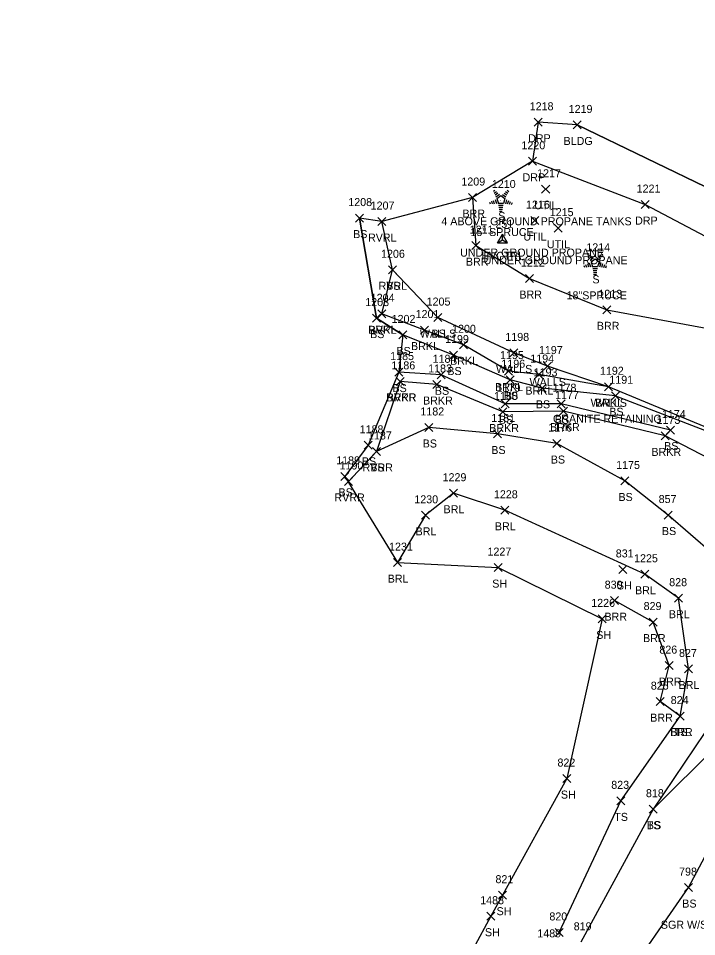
# Model space of a CAD drawing. Extents: x 1639430 to 1640195, y 612006 to 612917.
# Drawn here: x 1639596.7 to 1639766.2, y 612515.2 to 612744.6 of the extents above; entities that cross this region are included whole.
import ezdxf

# ---------------------------------------------------------------- set-up
doc = ezdxf.new("R2010")
doc.units = 0
for name, color, linetype in [('C_A', 7, 'Continuous'), ('C_I', 7, 'Continuous'), ('CPSM', 7, 'Continuous'), ('L_A', 7, 'Continuous'), ('L_C', 7, 'Continuous'), ('L_I', 7, 'Continuous'), ('L_TIC', 7, 'Continuous'), ('LABL', 7, 'Continuous'), ('LAWE', 7, 'Continuous'), ('LBC', 7, 'Continuous'), ('LELB', 7, 'Continuous'), ('LSOGP', 7, 'Continuous'), ('LTC', 7, 'Continuous'), ('LWS', 7, 'Continuous'), ('R_A', 7, 'Continuous'), ('R_C', 7, 'Continuous'), ('R_I', 7, 'Continuous'), ('R_TIC', 7, 'Continuous'), ('RDP', 7, 'Continuous'), ('U_A', 7, 'Continuous'), ('U_C', 7, 'Continuous'), ('U_I', 7, 'Continuous'), ('UDEFAULT', 7, 'Continuous')]:
    doc.layers.add(name, color=color, linetype=linetype)

msp = doc.modelspace()

# ---------------------------------------------------------------- linework, layer by layer
at = {"layer": 'CPSM'}
for p, q in [((1639716.47, 612688.55), (1639717.72, 612690.71)), ((1639718.97, 612688.55), (1639717.72, 612690.71)), ((1639717.72, 612689.27), (1639717.72, 612690.71)), ((1639716.47, 612688.55), (1639717.72, 612689.27)), ((1639716.47, 612688.55), (1639718.97, 612688.55)), ((1639717.72, 612689.27), (1639717.72, 612689.27)), ((1639717.72, 612689.27), (1639718.97, 612688.55))]:
    msp.add_line(p, q, dxfattribs=at)
at = {"layer": 'L_TIC'}
for points in [[(1639735.37, 612716.97), (1639737.37, 612718.97)], [(1639737.37, 612716.97), (1639735.37, 612718.97)], [(1639709.2, 612698.83), (1639711.2, 612700.83)], [(1639711.2, 612698.83), (1639709.2, 612700.83)], [(1639680.93, 612693.7), (1639682.93, 612695.7)], [(1639682.93, 612693.7), (1639680.93, 612695.7)], [(1639686.52, 612692.83), (1639688.52, 612694.83)], [(1639688.52, 612692.83), (1639686.52, 612694.83)], [(1639710.05, 612686.81), (1639712.05, 612688.81)], [(1639712.05, 612686.81), (1639710.05, 612688.81)], [(1639689.17, 612680.78), (1639691.17, 612682.78)], [(1639691.17, 612680.78), (1639689.17, 612682.78)], [(1639689.17, 612680.78), (1639691.17, 612682.78)], [(1639691.17, 612680.78), (1639689.17, 612682.78)], [(1639723.43, 612678.59), (1639725.43, 612680.59)], [(1639725.43, 612678.59), (1639723.43, 612680.59)], [(1639686.53, 612669.78), (1639688.53, 612671.78)], [(1639688.53, 612669.78), (1639686.53, 612671.78)], [(1639686.53, 612669.78), (1639688.53, 612671.78)], [(1639688.53, 612669.78), (1639686.53, 612671.78)], [(1639742.79, 612670.78), (1639744.79, 612672.78)], [(1639744.79, 612670.78), (1639742.79, 612672.78)], [(1639685.17, 612668.71), (1639687.17, 612670.71)], [(1639687.17, 612668.71), (1639685.17, 612670.71)], [(1639700.51, 612668.84), (1639702.51, 612670.84)], [(1639702.51, 612668.84), (1639700.51, 612670.84)], [(1639700.51, 612668.84), (1639702.51, 612670.84)], [(1639702.51, 612668.84), (1639700.51, 612670.84)], [(1639697.19, 612665.72), (1639699.19, 612667.72)], [(1639699.19, 612665.72), (1639697.19, 612667.72)], [(1639691.76, 612664.5), (1639693.76, 612666.5)], [(1639693.76, 612664.5), (1639691.76, 612666.5)], [(1639706.95, 612662.04), (1639708.95, 612664.04)], [(1639708.95, 612662.04), (1639706.95, 612664.04)], [(1639704.48, 612659.48), (1639706.48, 612661.48)], [(1639706.48, 612659.48), (1639704.48, 612661.48)], [(1639719.54, 612660.01), (1639721.54, 612662.01)], [(1639721.54, 612660.01), (1639719.54, 612662.01)], [(1639727.93, 612656.72), (1639729.93, 612658.72)], [(1639729.93, 612656.72), (1639727.93, 612658.72)], [(1639690.76, 612655.22), (1639692.76, 612657.22)], [(1639692.76, 612655.22), (1639690.76, 612657.22)], [(1639701.36, 612654.54), (1639703.36, 612656.54)], [(1639703.36, 612654.54), (1639701.36, 612656.54)], [(1639718.22, 612655.47), (1639720.22, 612657.47)], [(1639720.22, 612655.47), (1639718.22, 612657.47)], [(1639718.6, 612653.32), (1639720.6, 612655.32)], [(1639720.6, 612653.32), (1639718.6, 612655.32)], [(1639725.78, 612654.6), (1639727.78, 612656.6)], [(1639727.78, 612654.6), (1639725.78, 612656.6)], [(1639691.12, 612652.9), (1639693.12, 612654.9)], [(1639693.12, 612652.9), (1639691.12, 612654.9)], [(1639691.12, 612652.9), (1639693.12, 612654.9)], [(1639693.12, 612652.9), (1639691.12, 612654.9)], [(1639700.25, 612652.12), (1639702.25, 612654.12)], [(1639702.25, 612652.12), (1639700.25, 612654.12)], [(1639726.6, 612651.17), (1639728.6, 612653.17)], [(1639728.6, 612651.17), (1639726.6, 612653.17)], [(1639743.19, 612651.55), (1639745.19, 612653.55)], [(1639745.19, 612651.55), (1639743.19, 612653.55)], [(1639743.19, 612651.55), (1639745.19, 612653.55)], [(1639745.19, 612651.55), (1639743.19, 612653.55)], [(1639744.95, 612649.31), (1639746.95, 612651.31)], [(1639746.95, 612649.31), (1639744.95, 612651.31)], [(1639717.37, 612647.3), (1639719.37, 612649.3)], [(1639719.37, 612647.3), (1639717.37, 612649.3)], [(1639731.36, 612647.32), (1639733.36, 612649.32)], [(1639733.36, 612647.32), (1639731.36, 612649.32)], [(1639716.8, 612645.25), (1639718.8, 612647.25)], [(1639718.8, 612645.25), (1639716.8, 612647.25)], [(1639731.98, 612645.48), (1639733.98, 612647.48)], [(1639733.98, 612645.48), (1639731.98, 612647.48)], [(1639698.31, 612641.38), (1639700.31, 612643.38)], [(1639700.31, 612641.38), (1639698.31, 612643.38)], [(1639715.46, 612639.76), (1639717.46, 612641.76)], [(1639717.46, 612639.76), (1639715.46, 612641.76)], [(1639758.66, 612640.73), (1639760.66, 612642.73)], [(1639760.66, 612640.73), (1639758.66, 612642.73)], [(1639730.32, 612637.37), (1639732.32, 612639.37)], [(1639732.32, 612637.37), (1639730.32, 612639.37)], [(1639757.33, 612639.28), (1639759.33, 612641.28)], [(1639759.33, 612639.28), (1639757.33, 612641.28)], [(1639683.13, 612636.92), (1639685.13, 612638.92)], [(1639685.13, 612636.92), (1639683.13, 612638.92)], [(1639685.22, 612635.39), (1639687.22, 612637.39)], [(1639687.22, 612635.39), (1639685.22, 612637.39)], [(1639685.22, 612635.39), (1639687.22, 612637.39)], [(1639687.22, 612635.39), (1639685.22, 612637.39)], [(1639677.27, 612629.17), (1639679.27, 612631.17)], [(1639679.27, 612629.17), (1639677.27, 612631.17)], [(1639678.19, 612627.89), (1639680.19, 612629.89)], [(1639680.19, 612627.89), (1639678.19, 612629.89)], [(1639747.24, 612628.01), (1639749.24, 612630.01)], [(1639749.24, 612628.01), (1639747.24, 612630.01)], [(1639704.43, 612624.95), (1639706.43, 612626.95)], [(1639706.43, 612624.95), (1639704.43, 612626.95)], [(1639697.44, 612619.43), (1639699.44, 612621.43)], [(1639699.44, 612619.43), (1639697.44, 612621.43)], [(1639717.25, 612620.69), (1639719.25, 612622.69)], [(1639719.25, 612620.69), (1639717.25, 612622.69)], [(1639758.1, 612619.5), (1639760.1, 612621.5)], [(1639760.1, 612619.5), (1639758.1, 612621.5)], [(1639690.47, 612607.61), (1639692.47, 612609.61)], [(1639692.47, 612607.61), (1639690.47, 612609.61)], [(1639715.65, 612606.37), (1639717.65, 612608.37)], [(1639717.65, 612606.37), (1639715.65, 612608.37)], [(1639746.8, 612605.91), (1639748.8, 612607.91)], [(1639748.8, 612605.91), (1639746.8, 612607.91)], [(1639752.28, 612604.71), (1639754.28, 612606.71)], [(1639754.28, 612604.71), (1639752.28, 612606.71)], [(1639760.73, 612598.73), (1639762.73, 612600.73)], [(1639762.73, 612598.73), (1639760.73, 612600.73)], [(1639744.69, 612598.11), (1639746.69, 612600.11)], [(1639746.69, 612598.11), (1639744.69, 612600.11)], [(1639741.63, 612593.56), (1639743.63, 612595.56)], [(1639743.63, 612593.56), (1639741.63, 612595.56)], [(1639754.34, 612592.76), (1639756.34, 612594.76)], [(1639756.34, 612592.76), (1639754.34, 612594.76)], [(1639758.32, 612581.88), (1639760.32, 612583.88)], [(1639760.32, 612581.88), (1639758.32, 612583.88)], [(1639763.18, 612581.04), (1639765.18, 612583.04)], [(1639765.18, 612581.04), (1639763.18, 612583.04)], [(1639756.13, 612572.88), (1639758.13, 612574.88)], [(1639758.13, 612572.88), (1639756.13, 612574.88)], [(1639761.1, 612569.28), (1639763.1, 612571.28)], [(1639763.1, 612569.28), (1639761.1, 612571.28)], [(1639761.1, 612569.28), (1639763.1, 612571.28)], [(1639763.1, 612569.28), (1639761.1, 612571.28)], [(1639761.1, 612569.28), (1639763.1, 612571.28)], [(1639763.1, 612569.28), (1639761.1, 612571.28)], [(1639732.8, 612553.66), (1639734.8, 612555.66)], [(1639734.8, 612553.66), (1639732.8, 612555.66)], [(1639746.25, 612548.09), (1639748.25, 612550.09)], [(1639748.25, 612548.09), (1639746.25, 612550.09)], [(1639754.35, 612546.01), (1639756.35, 612548.01)], [(1639756.35, 612546.01), (1639754.35, 612548.01)], [(1639754.35, 612546.01), (1639756.35, 612548.01)], [(1639756.35, 612546.01), (1639754.35, 612548.01)], [(1639763.19, 612526.42), (1639765.19, 612528.42)], [(1639765.19, 612526.42), (1639763.19, 612528.42)], [(1639716.74, 612524.52), (1639718.74, 612526.52)], [(1639718.74, 612524.52), (1639716.74, 612526.52)], [(1639713.82, 612519.27), (1639715.82, 612521.27)], [(1639715.82, 612519.27), (1639713.82, 612521.27)], [(1639730.87, 612515.21), (1639732.87, 612517.21)], [(1639732.87, 612515.21), (1639730.87, 612517.21)]]:
    msp.add_lwpolyline(points, dxfattribs=at)
at = {"layer": 'LABL'}
for points in [[(1639710.2, 612699.83), (1639711.05, 612687.81), (1639724.43, 612679.59), (1639743.79, 612671.78), (1639774.03, 612666.16)], [(1639753.28, 612605.71), (1639718.25, 612621.69), (1639705.43, 612625.95), (1639698.44, 612620.43), (1639691.47, 612608.61)], [(1639761.73, 612599.73), (1639753.28, 612605.71)], [(1639762.1, 612570.28), (1639757.13, 612573.88), (1639759.32, 612582.88), (1639755.34, 612593.76), (1639745.69, 612599.11)], [(1639762.1, 612570.28), (1639764.18, 612582.04), (1639761.73, 612599.73)]]:
    msp.add_lwpolyline(points, dxfattribs=at)
at = {"layer": 'LAWE'}
for points in [[(1639687.53, 612670.78), (1639690.17, 612681.78), (1639687.52, 612693.83)], [(1639744.19, 612652.55), (1639726.78, 612655.6), (1639719.22, 612656.47), (1639707.95, 612663.04), (1639698.19, 612666.72), (1639687.53, 612670.78)], [(1639692.12, 612653.9), (1639686.22, 612636.39), (1639679.19, 612628.89)], [(1639758.33, 612640.28), (1639732.98, 612646.48), (1639717.8, 612646.25), (1639701.25, 612653.12), (1639692.12, 612653.9)], [(1639771.53, 612641.25), (1639744.19, 612652.55)], [(1639769.47, 612634.55), (1639758.33, 612640.28)]]:
    msp.add_lwpolyline(points, dxfattribs=at)
at = {"layer": 'LBC'}
msp.add_lwpolyline([(1639736.37, 612717.97), (1639805.32, 612684.7)], dxfattribs=at)
at = {"layer": 'LELB'}
for points in [[(1639745.95, 612650.31), (1639727.6, 612652.17), (1639719.6, 612654.32), (1639705.48, 612660.48), (1639692.76, 612665.5), (1639686.17, 612669.71), (1639681.93, 612694.7)], [(1639701.51, 612669.84), (1639690.17, 612681.78)], [(1639759.66, 612641.73), (1639732.36, 612648.32), (1639718.37, 612648.3), (1639702.36, 612655.54), (1639691.76, 612656.22), (1639684.13, 612637.92), (1639678.27, 612630.17)], [(1639745.95, 612650.31), (1639770.73, 612640.75)], [(1639748.24, 612629.01), (1639731.32, 612638.37), (1639716.46, 612640.76), (1639699.31, 612642.38), (1639686.22, 612636.39)], [(1639759.1, 612620.5), (1639748.24, 612629.01)], [(1639802.15, 612613.22), (1639795.18, 612610.67), (1639789.27, 612605.83), (1639775.86, 612605.95), (1639759.1, 612620.5)], [(1639798.64, 612584.24), (1639790.64, 612587.03), (1639783.43, 612585.38), (1639768.31, 612566.18), (1639755.35, 612547.01), (1639737.3, 612513.75)], [(1639798.04, 612571.86), (1639789.52, 612576.5), (1639780.86, 612572.87), (1639771.52, 612563.12), (1639755.35, 612547.01)], [(1639731.87, 612516.21), (1639747.25, 612549.09), (1639762.1, 612570.28)], [(1639746.81, 612502.27), (1639764.19, 612527.42), (1639772.98, 612544.04)]]:
    msp.add_lwpolyline(points, dxfattribs=at)
at = {"layer": 'LSOGP'}
for points in [[(1639832.37, 612746.66), (1639825.6, 612726.67), (1639820.71, 612717.04), (1639817.01, 612708.68), (1639805.32, 612684.7), (1639736.37, 612717.97), (1639726.62, 612718.64), (1639725.22, 612708.89), (1639710.2, 612699.83), (1639687.52, 612693.83), (1639681.93, 612694.7), (1639686.17, 612669.71), (1639692.76, 612665.5), (1639691.76, 612656.22), (1639684.13, 612637.92), (1639678.27, 612630.17), (1639691.47, 612608.61), (1639716.65, 612607.37), (1639742.63, 612594.56), (1639733.8, 612554.66), (1639717.74, 612525.52)], [(1639717.74, 612525.52), (1639714.82, 612520.27), (1639697.1, 612487.64), (1639680.04, 612445.97), (1639644.57, 612421.3), (1639635.96, 612403.52), (1639624.25, 612382.3), (1639608.49, 612348.06), (1639600.03, 612336.44), (1639596.7, 612332.58), (1639605.32, 612321.89), (1639618.65, 612314.53), (1639630.7, 612306.67)]]:
    msp.add_lwpolyline(points, dxfattribs=at)
at = {"layer": 'LTC'}
for p, q in [((1639715.45, 612701.42), (1639715.8, 612701.68)), ((1639715.65, 612700.95), (1639716.18, 612701.34)), ((1639718.47, 612701.31), (1639719.02, 612700.91)), ((1639718.84, 612701.66), (1639719.26, 612701.35)), ((1639714.93, 612698.91), (1639715.14, 612698.26)), ((1639715.39, 612699.13), (1639715.66, 612698.3)), ((1639715.84, 612699.35), (1639716.17, 612698.33)), ((1639715.86, 612700.49), (1639716.57, 612701)), ((1639716.07, 612700.02), (1639716.95, 612700.66)), ((1639716.3, 612699.57), (1639717.31, 612700.3)), ((1639716.3, 612699.57), (1639716.69, 612698.37)), ((1639717.31, 612700.3), (1639718.31, 612699.58)), ((1639717.73, 612700.61), (1639718.54, 612700.02)), ((1639718.31, 612699.58), (1639717.92, 612698.37)), ((1639718.1, 612700.96), (1639718.78, 612700.47)), ((1639718.74, 612699.3), (1639718.41, 612698.27)), ((1639719.19, 612699.05), (1639718.9, 612698.17)), ((1639714.48, 612698.7), (1639714.63, 612698.23)), ((1639717.92, 612698.37), (1639716.69, 612698.37)), ((1639717.88, 612697.87), (1639716.73, 612697.87)), ((1639717.79, 612697.37), (1639716.81, 612697.37)), ((1639717.71, 612696.87), (1639716.88, 612696.87)), ((1639719.63, 612698.8), (1639719.4, 612698.07)), ((1639720.08, 612698.55), (1639719.89, 612697.98)), ((1639717.63, 612696.37), (1639716.95, 612696.37)), ((1639738.98, 612685.6), (1639739.33, 612685.86)), ((1639739.19, 612685.13), (1639739.71, 612685.52)), ((1639739.39, 612684.67), (1639740.1, 612685.18)), ((1639741.63, 612685.14), (1639742.31, 612684.65)), ((1639742, 612685.49), (1639742.55, 612685.09)), ((1639742.37, 612685.84), (1639742.79, 612685.53)), ((1639738.01, 612682.88), (1639738.16, 612682.41)), ((1639738.46, 612683.09), (1639738.68, 612682.44)), ((1639738.92, 612683.31), (1639739.19, 612682.48)), ((1639739.37, 612683.53), (1639739.71, 612682.51)), ((1639739.6, 612684.2), (1639740.48, 612684.84)), ((1639739.83, 612683.75), (1639740.84, 612684.48)), ((1639739.83, 612683.75), (1639740.22, 612682.55)), ((1639740.84, 612684.48), (1639741.84, 612683.76)), ((1639741.26, 612684.79), (1639742.07, 612684.21)), ((1639741.84, 612683.76), (1639741.45, 612682.55)), ((1639742.28, 612683.49), (1639741.94, 612682.45)), ((1639742.72, 612683.23), (1639742.43, 612682.35)), ((1639743.16, 612682.98), (1639742.93, 612682.26)), ((1639741.45, 612682.55), (1639740.22, 612682.55)), ((1639741.41, 612682.05), (1639740.26, 612682.05)), ((1639741.32, 612681.55), (1639740.34, 612681.55)), ((1639741.24, 612681.05), (1639740.41, 612681.05)), ((1639741.16, 612680.55), (1639740.48, 612680.55)), ((1639743.61, 612682.73), (1639743.42, 612682.16))]:
    msp.add_line(p, q, dxfattribs=at)
at = {"layer": 'LWS'}
msp.add_lwpolyline([(1639744.19, 612652.55), (1639728.93, 612657.72), (1639720.54, 612661.01), (1639701.51, 612669.84)], dxfattribs=at)
at = {"layer": 'R_TIC'}
for points in [[(1639725.62, 612717.64), (1639727.62, 612719.64)], [(1639727.62, 612717.64), (1639725.62, 612719.64)], [(1639724.22, 612707.89), (1639726.22, 612709.89)], [(1639726.22, 612707.89), (1639724.22, 612709.89)], [(1639752.35, 612697.07), (1639754.35, 612699.07)], [(1639754.35, 612697.07), (1639752.35, 612699.07)]]:
    msp.add_lwpolyline(points, dxfattribs=at)
at = {"layer": 'RDP'}
msp.add_lwpolyline([(1639726.62, 612718.64), (1639725.22, 612708.89), (1639753.35, 612698.07), (1639780.33, 612683.86)], dxfattribs=at)
at = {"layer": 'UDEFAULT'}
for points in [[(1639727.49, 612700.9), (1639729.49, 612702.9)], [(1639729.49, 612700.9), (1639727.49, 612702.9)], [(1639724.75, 612693.07), (1639726.75, 612695.07)], [(1639726.75, 612693.07), (1639724.75, 612695.07)], [(1639730.64, 612691.18), (1639732.64, 612693.18)], [(1639732.64, 612691.18), (1639730.64, 612693.18)]]:
    msp.add_lwpolyline(points, dxfattribs=at)

# ---------------------------------------------------------------- texts
at = {"layer": 'C_A'}
msp.add_text('HVCTRL', height=2, dxfattribs=at).set_placement((1639712.41, 612684.27))
at = {"layer": 'C_I'}
msp.add_text('251', height=2, dxfattribs=at).set_placement((1639715.92, 612692.27))
at = {"layer": 'L_A'}
for s, p in [('BLDG', (1639732.96, 612712.97)), ('BRR', (1639707.69, 612694.83)), ('S', (1639716.64, 612694.21)), ('BS', (1639680.37, 612689.7)), ('RVRL', (1639684.09, 612688.83)), ('BRR', (1639708.54, 612682.81)), ('RVRL', (1639686.74, 612676.78)), ('BS', (1639688.62, 612676.78)), ('S', (1639740.17, 612678.39)), ('BRR', (1639721.92, 612674.59)), ('RVRL', (1639684.1, 612665.78)), ('BRKL', (1639684.18, 612665.78)), ('WALLS', (1639697.05, 612664.84)), ('BS', (1639699.95, 612664.84)), ('BRR', (1639741.28, 612666.78)), ('BS', (1639684.61, 612664.71)), ('BS', (1639691.2, 612660.5)), ('BRKL', (1639694.83, 612661.72)), ('BRKL', (1639704.6, 612658.04)), ('WALLS', (1639716.08, 612656.01)), ('BS', (1639703.92, 612655.48)), ('BS', (1639690.2, 612651.22)), ('BRKL', (1639715.86, 612651.47)), ('WALLS', (1639724.47, 612652.72)), ('RVRR', (1639688.63, 612648.9)), ('BRKR', (1639688.71, 612648.9)), ('BS', (1639700.8, 612650.54)), ('BS', (1639718.05, 612649.32)), ('BRKL', (1639723.42, 612650.6)), ('BRKR', (1639697.84, 612648.12)), ('BS', (1639726.04, 612647.17)), ('WALLS', (1639739.73, 612647.55)), ('BRKL', (1639740.83, 612647.55)), ('BS', (1639744.4, 612645.31)), ('BS', (1639716.81, 612643.3)), ('BS', (1639730.8, 612643.32)), ('BRKR', (1639714.39, 612641.25)), ('BRKR', (1639729.57, 612641.48)), ('BS', (1639697.75, 612637.38)), ('BS', (1639714.9, 612635.76)), ('BRKR', (1639754.92, 612635.28)), ('BS', (1639758.1, 612636.73)), ('BS', (1639682.57, 612632.92)), ('BS', (1639729.77, 612633.37)), ('RVRR', (1639682.73, 612631.39)), ('BS', (1639684.66, 612631.39)), ('RVRR', (1639675.7, 612623.89)), ('BS', (1639676.71, 612625.17)), ('BS', (1639746.68, 612624.01)), ('BRL', (1639702.97, 612620.95)), ('BRL', (1639715.8, 612616.69)), ('BRL', (1639695.98, 612615.43)), ('BS', (1639757.54, 612615.5)), ('BRL', (1639689.01, 612603.61)), ('SH', (1639715.13, 612602.37)), ('SH', (1639746.29, 612601.91)), ('BRL', (1639750.83, 612600.71)), ('BRR', (1639743.18, 612594.11)), ('BRL', (1639759.27, 612594.73)), ('SH', (1639741.12, 612589.56)), ('BRR', (1639752.83, 612588.76)), ('BRR', (1639756.8, 612577.88)), ('BRL', (1639761.72, 612577.04)), ('BRR', (1639754.62, 612568.88)), ('BRR', (1639759.59, 612565.28)), ('BRL', (1639759.65, 612565.28)), ('TS', (1639760.51, 612565.28)), ('SH', (1639732.29, 612549.66)), ('TS', (1639745.65, 612544.09)), ('TS', (1639753.76, 612542.01)), ('BS', (1639753.79, 612542.01)), ('SH', (1639716.22, 612520.52)), ('BS', (1639762.63, 612522.42)), ('SH', (1639713.31, 612515.27))]:
    msp.add_text(s, height=2, dxfattribs=at).set_placement(p)
at = {"layer": 'L_C'}
for s, p in [('15" SPRUCE', (1639709.69, 612690.21)), ('18"SPRUCE', (1639733.71, 612674.39)), ('GRANITE RETAINING', (1639730.31, 612643.55))]:
    msp.add_text(s, height=2, dxfattribs=at).set_placement(p)
at = {"layer": 'L_I'}
for s, p in [('1219', (1639734.24, 612720.97)), ('1209', (1639707.42, 612702.83)), ('1210', (1639715.04, 612702.21)), ('1208', (1639679.16, 612697.7)), ('1207', (1639684.75, 612696.83)), ('1211', (1639709.49, 612690.81)), ('1214', (1639738.65, 612686.39)), ('1206', (1639687.35, 612684.78)), ('1206', (1639687.35, 612684.78)), ('1212', (1639722.31, 612682.59)), ('1213', (1639741.66, 612674.78)), ('1203', (1639683.4, 612672.71)), ('1204', (1639684.76, 612673.78)), ('1204', (1639684.76, 612673.78)), ('1205', (1639698.74, 612672.84)), ('1205', (1639698.74, 612672.84)), ('1201', (1639695.98, 612669.72)), ('1202', (1639689.99, 612668.5)), ('1200', (1639705.1, 612666.04)), ('1199', (1639703.35, 612663.48)), ('1198', (1639718.41, 612664.01)), ('1197', (1639726.8, 612660.72)), ('1185', (1639689.63, 612659.22)), ('1184', (1639700.23, 612658.54)), ('1195', (1639717.09, 612659.47)), ('1194', (1639724.65, 612658.6)), ('1186', (1639689.94, 612656.9)), ('1186', (1639689.94, 612656.9)), ('1183', (1639699.12, 612656.12)), ('1196', (1639717.42, 612657.32)), ('1192', (1639742.06, 612655.55)), ('1192', (1639742.06, 612655.55)), ('1193', (1639725.48, 612655.17)), ('1191', (1639744.4, 612653.31)), ('1179', (1639716.23, 612651.3)), ('1178', (1639730.23, 612651.32)), ('1180', (1639715.59, 612649.25)), ('1177', (1639730.85, 612649.48)), ('1182', (1639697.18, 612645.38)), ('1174', (1639757.54, 612644.73)), ('1181', (1639714.9, 612643.76)), ('1173', (1639756.2, 612643.28)), ('1188', (1639682, 612640.92)), ('1176', (1639729.14, 612641.37)), ('1187', (1639684.09, 612639.39)), ('1187', (1639684.09, 612639.39)), ('1189', (1639676.14, 612633.17)), ('1190', (1639676.98, 612631.89)), ('1175', (1639746.11, 612632.01)), ('1229', (1639702.73, 612628.95)), ('1230', (1639695.66, 612623.43)), ('1228', (1639715.56, 612624.69)), ('857', (1639756.73, 612623.5)), ('1231', (1639689.34, 612611.61)), ('1227', (1639713.95, 612610.37)), ('831', (1639746.01, 612609.91)), ('1225', (1639750.59, 612608.71)), ('830', (1639743.24, 612602.11)), ('828', (1639759.37, 612602.73)), ('1226', (1639739.88, 612597.56)), ('829', (1639752.97, 612596.76)), ('826', (1639756.9, 612585.88)), ('827', (1639761.82, 612585.04)), ('825', (1639754.77, 612576.88)), ('824', (1639759.74, 612573.28)), ('824', (1639759.74, 612573.28)), ('824', (1639759.74, 612573.28)), ('822', (1639731.44, 612557.66)), ('823', (1639744.88, 612552.09)), ('818', (1639753.55, 612550.01)), ('818', (1639753.55, 612550.01)), ('798', (1639761.83, 612530.42)), ('821', (1639715.94, 612528.52)), ('1488', (1639712.13, 612523.27)), ('820', (1639729.42, 612519.21)), ('819', (1639735.5, 612516.75)), ('1489', (1639726.41, 612514.98))]:
    msp.add_text(s, height=2, dxfattribs=at).set_placement(p)
at = {"layer": 'LTC'}
for p in [(1639717.19, 612699.31), (1639740.72, 612683.49)]:
    msp.add_text('.', height=1.04, rotation=270, dxfattribs=at).set_placement(p)
at = {"layer": 'R_A'}
for p in [(1639724.11, 612713.64), (1639722.71, 612703.89), (1639750.84, 612693.07)]:
    msp.add_text('DRP', height=2, dxfattribs=at).set_placement(p)
at = {"layer": 'R_C'}
msp.add_text('SGR W/STEEL POST', height=2, dxfattribs=at).set_placement((1639757.28, 612517.14))
at = {"layer": 'R_I'}
for s, p in [('1218', (1639724.5, 612721.64)), ('1220', (1639722.44, 612711.89)), ('1221', (1639751.23, 612701.07))]:
    msp.add_text(s, height=2, dxfattribs=at).set_placement(p)
at = {"layer": 'U_A'}
for p in [(1639725.65, 612696.9), (1639722.92, 612689.07), (1639728.8, 612687.18)]:
    msp.add_text('UTIL', height=2, dxfattribs=at).set_placement(p)
at = {"layer": 'U_C'}
for s, p in [('4 ABOVE GROUND PROPANE TANKS', (1639702.42, 612692.9)), ('UNDER GROUND PROPANE', (1639707.11, 612685.07)), ('UNDER GROUND PROPANE', (1639712.99, 612683.18))]:
    msp.add_text(s, height=2, dxfattribs=at).set_placement(p)
at = {"layer": 'U_I'}
for s, p in [('1217', (1639726.36, 612704.9)), ('1216', (1639723.57, 612697.07)), ('1215', (1639729.51, 612695.18))]:
    msp.add_text(s, height=2, dxfattribs=at).set_placement(p)

doc.saveas('drawing.dxf')
